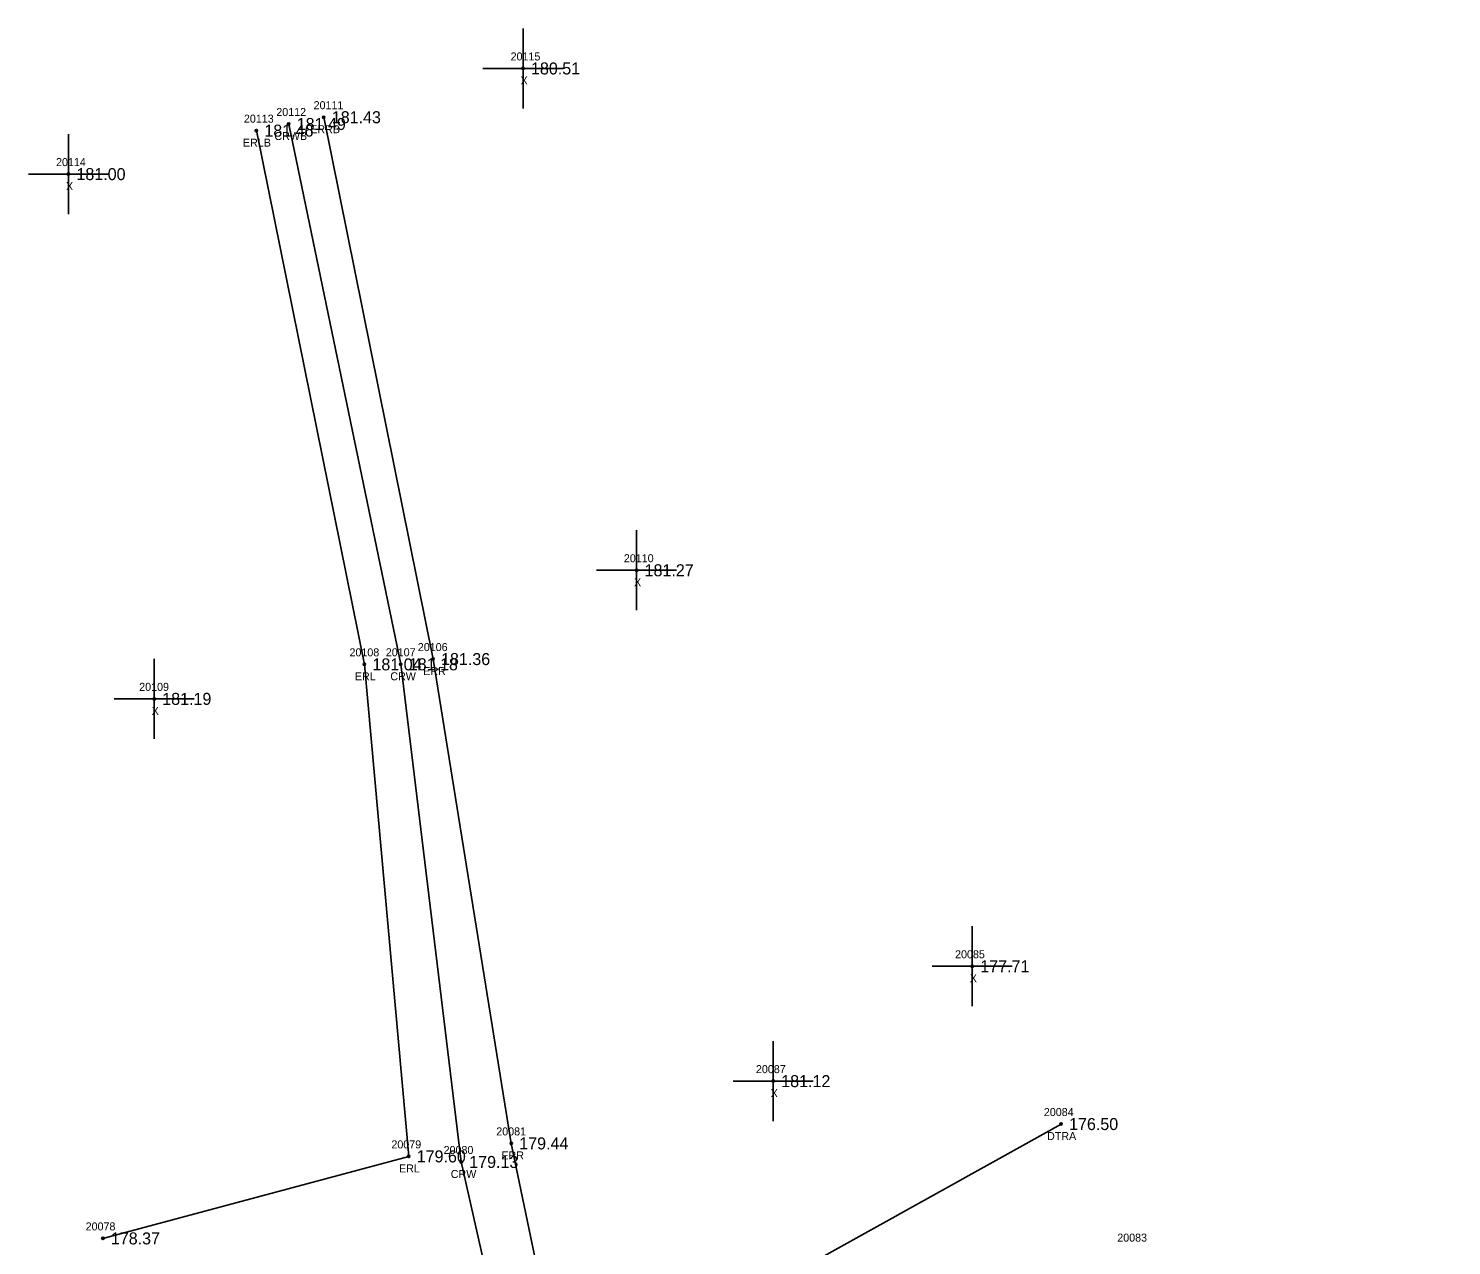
# Model space of a CAD drawing. Extents: x 1970726 to 1971567, y 794829 to 795775.
# Drawn here: x 1970754.5 to 1970932.3, y 795622.9 to 795774.9 of the extents above; entities that cross this region are included whole.
import ezdxf

# ---------------------------------------------------------------- set-up
doc = ezdxf.new("R2010")
doc.units = 0
for name, color, linetype in [('RD_DTM_BkLn1', 7, 'Continuous'), ('RD_EX_H2O', 7, 'Continuous'), ('RD_EX_H2O_txCode', 7, 'Continuous'), ('RD_EX_Misc', 7, 'Continuous'), ('RD_EX_Misc_txCode', 7, 'Continuous'), ('RD_EX_Road', 7, 'Continuous'), ('RD_EX_Road_txCode', 7, 'Continuous'), ('RD_EX_TX_H2O_ELEV', 7, 'Continuous'), ('RD_EX_TX_Misc_ELEV', 7, 'Continuous'), ('RD_EX_TX_Road_ELEV', 7, 'Continuous'), ('RD_HC_Survey_ELEV', 7, 'Continuous'), ('RD_HC_Survey_txCode', 7, 'Continuous'), ('RD_SMD_Locator', 7, 'Continuous')]:
    doc.layers.add(name, color=color, linetype=linetype)

msp = doc.modelspace()

# ---------------------------------------------------------------- linework, layer by layer
at = {"layer": 'RD_DTM_BkLn1'}
msp.add_lwpolyline([(1971548, 794856.6), (1971469.65, 794899.39), (1971398.6, 794938.78), (1971343.49, 794971.52), (1971282.15, 795020.93), (1971214.82, 795076.24), (1971168.26, 795117.15), (1971077.37, 795216.68), (1971014.25, 795285.1), (1970928, 795384.12), (1970874.41, 795450.05), (1970851.19, 795487.2), (1970834.94, 795528.12), (1970822.6, 795571.11), (1970808.56, 795633.3), (1970801.01, 795695.48), (1970787.01, 795762.98)], dxfattribs=at)
at = {"layer": 'RD_EX_H2O'}
msp.add_lwpolyline([(1970883.5, 795638.04), (1970834.18, 795610.6), (1970827.33, 795601.5), (1970831.66, 795579.46)], dxfattribs=at)
at = {"layer": 'RD_EX_Misc'}
for p, q in [((1970816.28, 795764.92), (1970816.28, 795774.92)), ((1970811.28, 795769.92), (1970821.28, 795769.92)), ((1970759.49, 795751.72), (1970759.49, 795761.72)), ((1970754.49, 795756.72), (1970764.49, 795756.72)), ((1970830.47, 795702.23), (1970830.47, 795712.23)), ((1970825.47, 795707.23), (1970835.47, 795707.23)), ((1970770.21, 795686.16), (1970770.21, 795696.16)), ((1970765.21, 795691.16), (1970775.21, 795691.16)), ((1970872.41, 795652.75), (1970872.41, 795662.75)), ((1970867.41, 795657.75), (1970877.41, 795657.75)), ((1970847.54, 795638.4), (1970847.54, 795648.4)), ((1970842.54, 795643.4), (1970852.54, 795643.4))]:
    msp.add_line(p, q, dxfattribs=at)
at = {"layer": 'RD_EX_Road'}
for points in [[(1971550.5, 794861.13), (1971472.2, 794904.32), (1971401.49, 794943.08), (1971346.58, 794975.73), (1971286.05, 795024.56), (1971217.92, 795079.41), (1971172.76, 795121.06), (1971082.31, 795221.27), (1971017.96, 795288.13), (1970931.75, 795387.33), (1970878.11, 795452.95), (1970856.35, 795489.48), (1970840.29, 795529.45), (1970827.57, 795574.31), (1970814.81, 795635.62), (1970805.04, 795696.13), (1970791.39, 795763.83)], [(1970763.79, 795623.75), (1970802, 795634), (1970796.47, 795695.47), (1970782.97, 795762.15)]]:
    msp.add_lwpolyline(points, dxfattribs=at)
at = {"layer": 'RD_SMD_Locator'}
for centre in [(1970816.28, 795769.92), (1970791.39, 795763.83), (1970782.97, 795762.15), (1970787.01, 795762.98), (1970759.49, 795756.72), (1970830.47, 795707.23), (1970805.04, 795696.13), (1970796.47, 795695.47), (1970801.01, 795695.48), (1970770.21, 795691.16), (1970872.41, 795657.75), (1970847.54, 795643.4), (1970883.5, 795638.04), (1970814.81, 795635.62), (1970802, 795634), (1970808.56, 795633.3), (1970763.79, 795623.75)]:
    msp.add_circle(centre, 0.15, dxfattribs=at)

# ---------------------------------------------------------------- texts
at = {"layer": 'RD_EX_H2O_txCode'}
for s, p in [('20084', (1970881.35, 795639.04)), ('DTRA', (1970881.75, 795636.04)), ('20083', (1970890.52, 795623.35))]:
    msp.add_text(s, height=1, dxfattribs=at).set_placement(p)
at = {"layer": 'RD_EX_Misc_txCode'}
for s, p in [('20115', (1970814.73, 795770.92)), ('X', (1970815.97, 795767.92)), ('20114', (1970757.94, 795757.72)), ('X', (1970759.18, 795754.72)), ('20110', (1970828.88, 795708.23)), ('X', (1970830.15, 795705.23)), ('20109', (1970768.33, 795692.16)), ('X', (1970769.89, 795689.16)), ('20085', (1970870.26, 795658.75)), ('X', (1970872.1, 795655.75)), ('20087', (1970845.38, 795644.4)), ('X', (1970847.22, 795641.4))]:
    msp.add_text(s, height=1, dxfattribs=at).set_placement(p)
at = {"layer": 'RD_EX_Road_txCode'}
for s, p in [('20111', (1970790.12, 795764.83)), ('20113', (1970781.41, 795763.15)), ('ERRB', (1970789.69, 795761.83)), ('ERLB', (1970781.29, 795760.15)), ('20106', (1970803.14, 795697.13)), ('20108', (1970794.6, 795696.47)), ('ERL', (1970795.27, 795693.47)), ('ERR', (1970803.81, 795694.13)), ('20081', (1970812.94, 795636.62)), ('20079', (1970799.84, 795635)), ('ERR', (1970813.58, 795633.62)), ('ERL', (1970800.79, 795632)), ('20078', (1970761.64, 795624.75))]:
    msp.add_text(s, height=1, dxfattribs=at).set_placement(p)
at = {"layer": 'RD_EX_TX_H2O_ELEV'}
msp.add_text('176.50', height=1.5, dxfattribs=at).set_placement((1970884.5, 795637.29))
at = {"layer": 'RD_EX_TX_Misc_ELEV'}
for s, p in [('180.51', (1970817.28, 795769.17)), ('181.00', (1970760.49, 795755.97)), ('181.27', (1970831.47, 795706.48)), ('181.19', (1970771.21, 795690.41)), ('177.71', (1970873.41, 795657)), ('181.12', (1970848.54, 795642.65))]:
    msp.add_text(s, height=1.5, dxfattribs=at).set_placement(p)
at = {"layer": 'RD_EX_TX_Road_ELEV'}
for s, p in [('181.43', (1970792.39, 795763.08)), ('181.46', (1970783.97, 795761.4)), ('181.04', (1970797.47, 795694.72)), ('181.36', (1970806.04, 795695.38)), ('179.44', (1970815.81, 795634.87)), ('179.60', (1970803, 795633.25)), ('178.37', (1970764.79, 795623))]:
    msp.add_text(s, height=1.5, dxfattribs=at).set_placement(p)
at = {"layer": 'RD_HC_Survey_ELEV'}
for s, p in [('181.49', (1970788.01, 795762.23)), ('181.18', (1970802.01, 795694.73)), ('179.13', (1970809.56, 795632.55))]:
    msp.add_text(s, height=1.5, dxfattribs=at).set_placement(p)
at = {"layer": 'RD_HC_Survey_txCode'}
for s, p in [('20112', (1970785.46, 795763.98)), ('CRWB', (1970785.22, 795760.98)), ('20107', (1970799.14, 795696.48)), ('CRW', (1970799.7, 795693.48)), ('20080', (1970806.36, 795634.3)), ('CRW', (1970807.25, 795631.3))]:
    msp.add_text(s, height=1, dxfattribs=at).set_placement(p)

doc.saveas('drawing.dxf')
